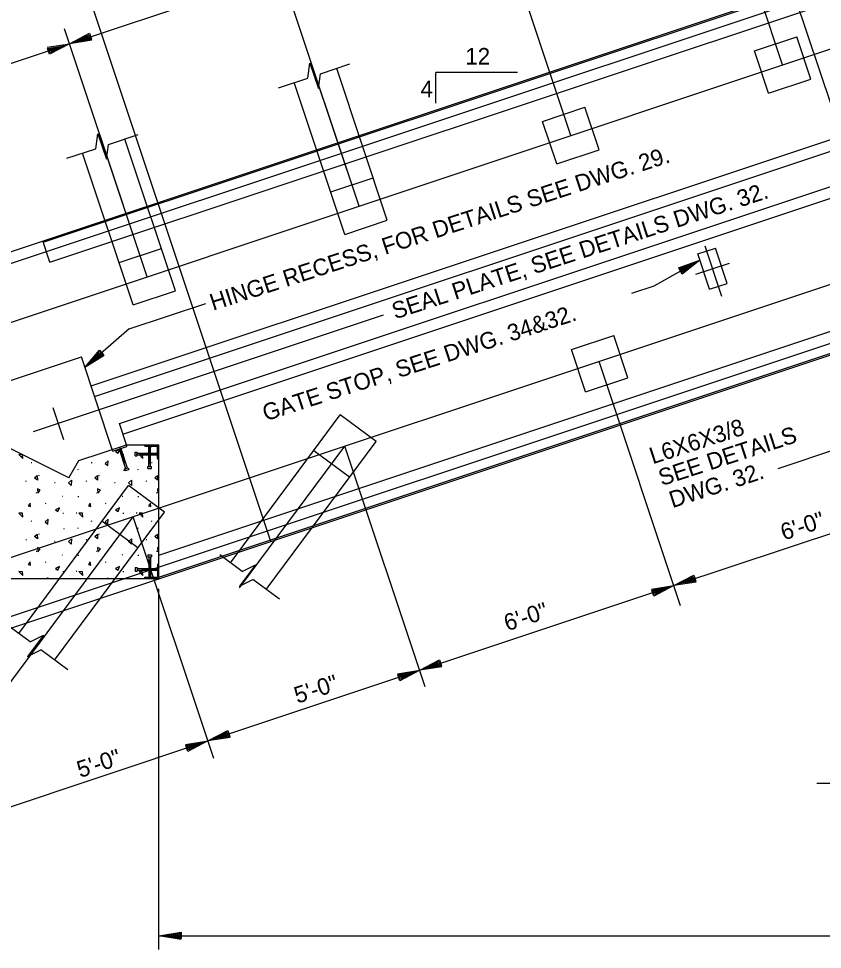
# Model space of a CAD drawing. Extents: x 6 to 106, y 3 to 74.
# Drawn here: x 20.04 to 38.04, y 38.69 to 59.54 of the extents above; entities that cross this region are included whole.
import ezdxf

# ---------------------------------------------------------------- set-up
doc = ezdxf.new("R2010")
doc.units = 0
for name, color, linetype in [('Level 13', 7, 'Continuous'), ('Level 22', 7, 'Continuous'), ('Level 25', 7, 'Continuous'), ('Level 44', 7, 'Continuous'), ('Level 50', 7, 'Continuous')]:
    doc.layers.add(name, color=color, linetype=linetype)

msp = doc.modelspace()

# ---------------------------------------------------------------- linework, layer by layer
at = {"layer": 'Level 13'}
for points in [[(26.515, 58.206), (26.562, 58.538), (26.751, 57.969), (26.799, 58.3)], [(21.767, 56.623), (21.813, 56.955), (22.003, 56.386), (22.05, 56.717)], [(25.042, 47.151), (25.341, 47.303), (24.984, 46.822), (25.282, 46.973)], [(20.293, 45.574), (20.591, 45.726), (20.234, 45.245), (20.533, 45.396)]]:
    msp.add_lwpolyline(points, dxfattribs=at)
at = {"layer": 'Level 22'}
for p, q in [((31.214, 58.332), (29.383, 58.332)), ((29.383, 57.644), (29.383, 58.332)), ((34.27, 53.552), (35.297, 54.126)), ((21.163, 49.25), (14.561, 52.551)), ((22.513, 52.584), (21.523, 51.723)), ((24.782, 47.344), (27.242, 50.66)), ((28.045, 50.064), (27.242, 50.66)), ((25.585, 46.748), (28.045, 50.064)), ((22.287, 49.892), (22.432, 49.457)), ((22.293, 49.938), (22.413, 49.579)), ((22.326, 49.905), (22.471, 49.471)), ((24.988, 46.782), (27.345, 49.961)), ((27.449, 49.261), (26.646, 49.857)), ((22.412, 49.451), (22.425, 49.411)), ((22.491, 49.477), (22.504, 49.438)), ((20.039, 45.763), (22.498, 49.079)), ((23.302, 48.483), (22.498, 49.079)), ((16.306, 39.892), (22.602, 48.379)), ((20.842, 45.167), (23.302, 48.483)), ((22.706, 47.68), (21.903, 48.276)), ((25.042, 47.151), (24.541, 47.523)), ((25.881, 46.529), (25.282, 46.973)), ((20.293, 45.574), (19.797, 45.941)), ((21.137, 44.948), (20.533, 45.396)), ((37.914, 42.409), (44.306, 42.409))]:
    msp.add_line(p, q, dxfattribs=at)
for centre, start, end in [((22.878, 49.991), 180, 270), ((23.18, 49.689), 180, 270), ((23.18, 47.293), 90, 180), ((22.878, 46.991), 90, 180)]:
    msp.add_arc(centre, 0.0313, start, end, dxfattribs=at)
at = {"layer": 'Level 25'}
for p, q in [((37.149, 58.499), (35.27, 64.135)), ((32.405, 56.918), (30.545, 62.497)), ((14.561, 52.551), (41.18, 61.424)), ((20.588, 54.527), (41.19, 61.394)), ((23.155, 55.416), (21.14, 61.463)), ((14.835, 52.378), (41.18, 61.16)), ((20.736, 54.082), (41.18, 60.897)), ((27.662, 55.336), (25.803, 60.913)), ((21.179, 58.973), (25.922, 60.554)), ((9.584, 49.31), (41.18, 59.843)), ((39.833, 52.818), (37.44, 59.996)), ((22.918, 53.755), (21.067, 59.31)), ((36.516, 58.815), (37.465, 59.131)), ((37.781, 58.182), (37.465, 59.131)), ((16.436, 57.392), (21.179, 58.973)), ((36.832, 57.866), (36.516, 58.815)), ((27.662, 55.336), (26.6, 58.522)), ((26.799, 58.3), (27.459, 58.521)), ((28.294, 55.02), (27.161, 58.421)), ((25.861, 57.988), (26.515, 58.206)), ((36.832, 57.866), (37.781, 58.182)), ((27.345, 54.704), (26.212, 58.105)), ((21.661, 51.309), (41.18, 57.815)), ((21.74, 51.072), (41.18, 57.552)), ((31.773, 57.234), (32.721, 57.55)), ((33.038, 56.601), (32.721, 57.55)), ((32.089, 56.285), (31.773, 57.234)), ((22.918, 53.755), (21.856, 56.941)), ((22.05, 56.717), (22.716, 56.939)), ((22.293, 50.465), (41.18, 56.761)), ((23.551, 53.439), (22.417, 56.84)), ((21.118, 56.407), (21.767, 56.623)), ((22.602, 53.123), (21.468, 56.524)), ((32.089, 56.285), (33.038, 56.601)), ((22.372, 50.228), (41.18, 56.498)), ((27.029, 55.653), (27.978, 55.969)), ((25.685, 47.826), (23.155, 55.416)), ((27.345, 54.704), (28.294, 55.02)), ((11.145, 44.56), (41.18, 54.572)), ((20.736, 54.082), (20.578, 54.556)), ((35.787, 53.314), (35.412, 54.44)), ((22.286, 54.072), (23.235, 54.388)), ((35.251, 54.265), (35.646, 54.396)), ((35.514, 53.474), (35.251, 54.265)), ((35.909, 53.606), (35.646, 54.396)), ((35.206, 53.811), (35.957, 54.061)), ((35.514, 53.474), (35.909, 53.606)), ((22.602, 53.123), (23.551, 53.439)), ((23.18, 47.518), (41.18, 53.518)), ((33.769, 53.385), (34.27, 53.552)), ((15.882, 44.822), (41.18, 53.255)), ((15.961, 44.585), (41.18, 52.991)), ((22.513, 52.584), (24.227, 53.155)), ((23.18, 47.024), (41.171, 53.021)), ((20.37, 50.286), (28.212, 52.9)), ((32.421, 52.125), (33.37, 52.441)), ((33.686, 51.493), (33.37, 52.441)), ((19.368, 51.269), (21.443, 51.961)), ((22.135, 49.886), (21.443, 51.961)), ((32.738, 51.176), (32.421, 52.125)), ((34.862, 46.386), (33.038, 51.858)), ((32.738, 51.176), (33.686, 51.493)), ((21.047, 50.101), (20.808, 50.816)), ((22.451, 49.991), (22.293, 50.465)), ((21.386, 49.636), (22.451, 49.991)), ((22.148, 49.846), (22.135, 49.886)), ((22.148, 49.846), (22.464, 49.952)), ((22.451, 49.991), (23.18, 49.991)), ((22.464, 49.952), (22.451, 49.991)), ((22.878, 49.96), (23.149, 49.96)), ((22.951, 49.502), (22.951, 49.96)), ((22.972, 49.561), (22.972, 49.991)), ((22.993, 49.502), (22.993, 49.96)), ((23.149, 49.689), (23.149, 49.96)), ((23.18, 46.991), (23.18, 49.991)), ((29.144, 44.565), (27.345, 49.961)), ((37.051, 49.461), (38.409, 49.914)), ((21.163, 49.25), (21.386, 49.636)), ((22.649, 49.741), (22.649, 49.824)), ((22.649, 49.824), (22.691, 49.824)), ((22.649, 49.741), (22.691, 49.741)), ((22.691, 49.741), (22.691, 49.824)), ((22.691, 49.804), (23.149, 49.804)), ((22.691, 49.762), (23.149, 49.762)), ((22.799, 49.783), (23.18, 49.783)), ((22.412, 49.451), (22.491, 49.477)), ((22.425, 49.411), (22.504, 49.438)), ((22.93, 49.502), (23.014, 49.502)), ((22.93, 49.46), (22.93, 49.502)), ((22.93, 49.46), (23.014, 49.46)), ((23.014, 49.46), (23.014, 49.502)), ((34.712, 46.835), (40.404, 48.732)), ((24.407, 42.965), (22.602, 48.379)), ((22.93, 47.522), (23.014, 47.522)), ((22.93, 47.522), (22.93, 47.481)), ((22.93, 47.481), (23.014, 47.481)), ((22.951, 47.481), (22.951, 47.022)), ((22.972, 47.421), (22.972, 46.991)), ((22.993, 47.481), (22.993, 47.022)), ((23.014, 47.522), (23.014, 47.481)), ((22.649, 47.241), (22.649, 47.158)), ((22.649, 47.241), (22.691, 47.241)), ((22.649, 47.158), (22.691, 47.158)), ((22.691, 47.241), (22.691, 47.158)), ((22.691, 47.22), (23.149, 47.22)), ((22.691, 47.179), (23.149, 47.179)), ((22.799, 47.199), (23.18, 47.199)), ((23.149, 47.293), (23.149, 47.022)), ((19.18, 46.991), (23.18, 46.991)), ((22.878, 47.022), (23.149, 47.022)), ((23.18, 38.686), (23.18, 46.763)), ((29.02, 44.938), (34.712, 46.835)), ((24.276, 43.356), (29.02, 44.938)), ((19.533, 41.775), (24.276, 43.356)), ((23.18, 38.991), (59.18, 38.991))]:
    msp.add_line(p, q, dxfattribs=at)
at = {"layer": 'Level 44'}
for p, q in [((22.391, 49.766), (22.373, 49.766)), ((22.69, 49.772), (22.673, 49.772)), ((20.336, 49.586), (20.318, 49.589)), ((21.369, 49.435), (21.356, 49.43)), ((21.682, 49.586), (21.665, 49.589)), ((22.405, 49.417), (22.387, 49.412)), ((22.716, 49.435), (22.703, 49.43)), ((23.029, 49.586), (23.012, 49.589)), ((20.505, 49.293), (20.49, 49.302)), ((21.852, 49.293), (21.837, 49.302)), ((20.215, 49.169), (20.201, 49.176)), ((20.855, 49.137), (20.84, 49.136)), ((21.562, 49.169), (21.547, 49.176)), ((22.201, 49.137), (22.187, 49.136)), ((22.908, 49.169), (22.894, 49.176)), ((20.445, 48.91), (20.432, 48.911)), ((21.023, 48.832), (21.01, 48.835)), ((21.382, 48.821), (21.364, 48.821)), ((21.792, 48.91), (21.779, 48.911)), ((22.37, 48.832), (22.356, 48.835)), ((22.728, 48.821), (22.71, 48.821)), ((23.139, 48.91), (23.125, 48.911)), ((20.646, 48.675), (20.63, 48.667)), ((21.992, 48.675), (21.976, 48.667)), ((21.044, 48.454), (21.026, 48.454)), ((21.343, 48.46), (21.326, 48.46)), ((22.391, 48.454), (22.373, 48.454)), ((22.69, 48.46), (22.673, 48.46)), ((20.336, 48.274), (20.318, 48.277)), ((21.682, 48.274), (21.665, 48.277)), ((23.029, 48.274), (23.012, 48.277)), ((20.505, 47.982), (20.49, 47.991)), ((21.059, 48.105), (21.041, 48.1)), ((21.369, 48.123), (21.356, 48.118)), ((21.852, 47.982), (21.837, 47.991)), ((22.405, 48.105), (22.387, 48.1)), ((22.716, 48.123), (22.703, 48.118)), ((20.215, 47.858), (20.201, 47.864)), ((20.855, 47.826), (20.84, 47.824)), ((21.562, 47.858), (21.547, 47.864)), ((22.201, 47.826), (22.187, 47.824)), ((22.908, 47.858), (22.894, 47.864)), ((20.445, 47.599), (20.432, 47.6)), ((21.792, 47.599), (21.779, 47.6)), ((23.139, 47.599), (23.125, 47.6)), ((20.646, 47.364), (20.63, 47.356)), ((21.023, 47.521), (21.01, 47.523)), ((21.382, 47.509), (21.364, 47.509)), ((21.992, 47.364), (21.976, 47.356)), ((22.37, 47.521), (22.356, 47.523)), ((22.728, 47.509), (22.71, 47.509)), ((21.044, 47.142), (21.026, 47.142)), ((21.343, 47.149), (21.326, 47.149)), ((22.391, 47.142), (22.373, 47.142)), ((22.69, 47.149), (22.673, 47.149))]:
    msp.add_line(p, q, dxfattribs=at)
for points in [[(22.265, 49.805), (22.297, 49.886), (22.208, 49.843)], [(20.121, 49.768), (20.041, 49.772), (20.128, 49.683)], [(22.046, 49.634), (21.978, 49.574), (22.035, 49.526)], [(22.815, 49.768), (22.735, 49.772), (22.821, 49.683)], [(20.458, 49.199), (20.394, 49.247), (20.455, 49.302)], [(21.805, 49.199), (21.741, 49.247), (21.802, 49.302)], [(23.151, 49.199), (23.087, 49.247), (23.149, 49.302)], [(20.465, 48.906), (20.522, 48.97), (20.458, 49.004)], [(21.215, 49.079), (21.153, 49.136), (21.222, 49.197)], [(21.811, 48.906), (21.868, 48.97), (21.805, 49.004)], [(22.562, 49.079), (22.5, 49.136), (22.568, 49.197)], [(20.304, 48.608), (20.295, 48.681), (20.254, 48.62)], [(21.651, 48.608), (21.642, 48.681), (21.601, 48.62)], [(22.998, 48.608), (22.988, 48.681), (22.947, 48.62)], [(20.121, 48.456), (20.041, 48.46), (20.128, 48.372)], [(20.918, 48.493), (20.95, 48.575), (20.862, 48.532)], [(21.468, 48.456), (21.388, 48.46), (21.475, 48.372)], [(22.265, 48.493), (22.297, 48.575), (22.208, 48.532)], [(22.815, 48.456), (22.735, 48.46), (22.821, 48.372)], [(20.7, 48.322), (20.631, 48.262), (20.688, 48.215)], [(22.046, 48.322), (21.978, 48.262), (22.035, 48.215)], [(20.458, 47.887), (20.394, 47.936), (20.455, 47.99)], [(21.805, 47.887), (21.741, 47.936), (21.802, 47.99)], [(23.151, 47.887), (23.087, 47.936), (23.149, 47.99)], [(21.215, 47.767), (21.153, 47.824), (21.222, 47.885)], [(22.562, 47.767), (22.5, 47.824), (22.568, 47.885)], [(20.465, 47.594), (20.522, 47.658), (20.458, 47.692)], [(21.811, 47.594), (21.868, 47.658), (21.805, 47.692)], [(20.304, 47.296), (20.295, 47.369), (20.254, 47.308)], [(21.651, 47.296), (21.642, 47.369), (21.601, 47.308)], [(22.998, 47.296), (22.988, 47.369), (22.947, 47.308)], [(20.121, 47.144), (20.041, 47.149), (20.128, 47.06)], [(20.918, 47.181), (20.95, 47.263), (20.862, 47.22)], [(21.468, 47.144), (21.388, 47.149), (21.475, 47.06)], [(22.265, 47.181), (22.297, 47.263), (22.208, 47.22)], [(22.815, 47.144), (22.735, 47.149), (22.821, 47.06)]]:
    msp.add_lwpolyline(points, close=True, dxfattribs=at)
for points in [[(22.988, 49.991), (22.947, 49.931), (22.998, 49.919)], [(22.998, 49.919), (22.989, 49.991)], [(23.18, 48.988), (23.151, 49.004), (23.158, 48.906)], [(23.158, 48.906), (23.18, 48.931)], [(23.18, 47.676), (23.151, 47.692), (23.158, 47.594)], [(23.158, 47.594), (23.18, 47.619)], [(20.7, 47.01), (20.678, 46.991)], [(20.698, 46.991), (20.7, 47.01)], [(22.046, 47.01), (22.025, 46.991)], [(22.044, 46.991), (22.046, 47.01)]]:
    msp.add_lwpolyline(points, dxfattribs=at)
at = {"layer": 'Level 50'}
for p, q in [((21.311, 59.017), (21.311, 59.017)), ((21.047, 58.929), (21.047, 58.929)), ((21.179, 58.973), (21.179, 58.973)), ((21.179, 58.973), (21.179, 58.973)), ((35.176, 54.058), (35.176, 54.058)), ((35.297, 54.126), (35.297, 54.126)), ((21.523, 51.723), (21.523, 51.723)), ((21.627, 51.813), (21.627, 51.813)), ((34.58, 46.791), (34.58, 46.791)), ((34.712, 46.835), (34.712, 46.835)), ((34.712, 46.835), (34.712, 46.835)), ((34.843, 46.879), (34.843, 46.879)), ((28.888, 44.894), (28.888, 44.894)), ((29.02, 44.938), (29.02, 44.938)), ((29.02, 44.938), (29.02, 44.938)), ((29.151, 44.981), (29.151, 44.981)), ((24.408, 43.4), (24.408, 43.4)), ((24.145, 43.313), (24.145, 43.313)), ((24.276, 43.356), (24.276, 43.356)), ((24.276, 43.356), (24.276, 43.356)), ((23.18, 38.991), (23.18, 38.991)), ((23.319, 38.991), (23.319, 38.991))]:
    msp.add_line(p, q, dxfattribs=at)
for points in [[(21.678, 59.052), (21.179, 58.973), (21.626, 59.209), (21.671, 59.075), (21.311, 59.017), (21.614, 59.177), (21.643, 59.091), (21.437, 59.059), (21.602, 59.145), (21.614, 59.11), (21.569, 59.103)], [(20.68, 58.894), (21.179, 58.973), (20.732, 58.737), (20.687, 58.871), (21.047, 58.929), (20.744, 58.769), (20.715, 58.855), (20.921, 58.887), (20.756, 58.801), (20.744, 58.836), (20.789, 58.843)], [(34.821, 53.955), (35.297, 54.126), (34.902, 53.81), (34.833, 53.934), (35.176, 54.058), (34.907, 53.844), (34.863, 53.923), (35.059, 53.993), (34.913, 53.878), (34.895, 53.91), (34.938, 53.925)], [(21.953, 51.987), (21.523, 51.723), (21.845, 52.112), (21.938, 52.005), (21.627, 51.813), (21.846, 52.078), (21.906, 52.01), (21.728, 51.901), (21.848, 52.044), (21.872, 52.016), (21.833, 51.992)], [(35.211, 46.914), (34.712, 46.835), (35.159, 47.071), (35.204, 46.937), (34.843, 46.879), (35.147, 47.039), (35.176, 46.953), (34.97, 46.921), (35.135, 47.007), (35.147, 46.972), (35.102, 46.965)], [(34.213, 46.756), (34.712, 46.835), (34.265, 46.599), (34.22, 46.733), (34.58, 46.791), (34.277, 46.631), (34.248, 46.717), (34.454, 46.749), (34.289, 46.663), (34.277, 46.698), (34.322, 46.705)], [(29.519, 45.017), (29.02, 44.938), (29.467, 45.174), (29.511, 45.04), (29.151, 44.981), (29.455, 45.142), (29.484, 45.056), (29.278, 45.024), (29.443, 45.11), (29.455, 45.074), (29.409, 45.067)], [(28.521, 44.858), (29.02, 44.938), (28.573, 44.701), (28.528, 44.836), (28.888, 44.894), (28.585, 44.733), (28.556, 44.819), (28.762, 44.852), (28.596, 44.766), (28.585, 44.801), (28.63, 44.808)], [(24.776, 43.436), (24.276, 43.356), (24.723, 43.593), (24.768, 43.458), (24.408, 43.4), (24.712, 43.56), (24.74, 43.474), (24.534, 43.442), (24.7, 43.528), (24.712, 43.493), (24.666, 43.486)], [(23.777, 43.277), (24.276, 43.356), (23.829, 43.12), (23.785, 43.254), (24.145, 43.313), (23.841, 43.152), (23.813, 43.238), (24.018, 43.27), (23.853, 43.184), (23.841, 43.22), (23.887, 43.227)], [(23.679, 38.908), (23.18, 38.991), (23.679, 39.074), (23.679, 38.932), (23.319, 38.991), (23.658, 39.047), (23.658, 38.956), (23.452, 38.991), (23.636, 39.02), (23.636, 38.983), (23.591, 38.991)]]:
    msp.add_lwpolyline(points, dxfattribs=at)

# ---------------------------------------------------------------- texts
at = {"layer": 'Level 22'}
for s, height, p in [('12', 0.3733, (30.043, 58.507)), ('4', 0.373, (29.038, 57.776))]:
    msp.add_text(s, height=height, dxfattribs=at).set_placement(p)
for s, height, p in [('HINGE RECESS, FOR DETAILS SEE DWG. 29.', 0.37333, (24.393, 52.991)), ('SEAL PLATE, SEE DETAILS DWG. 32.', 0.37333, (28.47, 52.798)), ('GATE STOP, SEE DWG. 34&32.', 0.37333, (25.571, 50.515)), ('L6X6X3/8', 0.3733, (34.24, 49.552)), ('SEE DETAILS ', 0.37333, (34.441, 49.064)), ('DWG. 32.', 0.3733, (34.681, 48.569)), ('6\'-0"', 0.3733, (37.177, 47.844)), ('6\'-0"', 0.3733, (30.981, 45.811)), ('5\'-0"', 0.3733, (26.281, 44.189)), ('5\'-0"', 0.3733, (21.415, 42.525))]:
    msp.add_text(s, height=height, rotation=18, dxfattribs=at).set_placement(p)

doc.saveas('drawing.dxf')
